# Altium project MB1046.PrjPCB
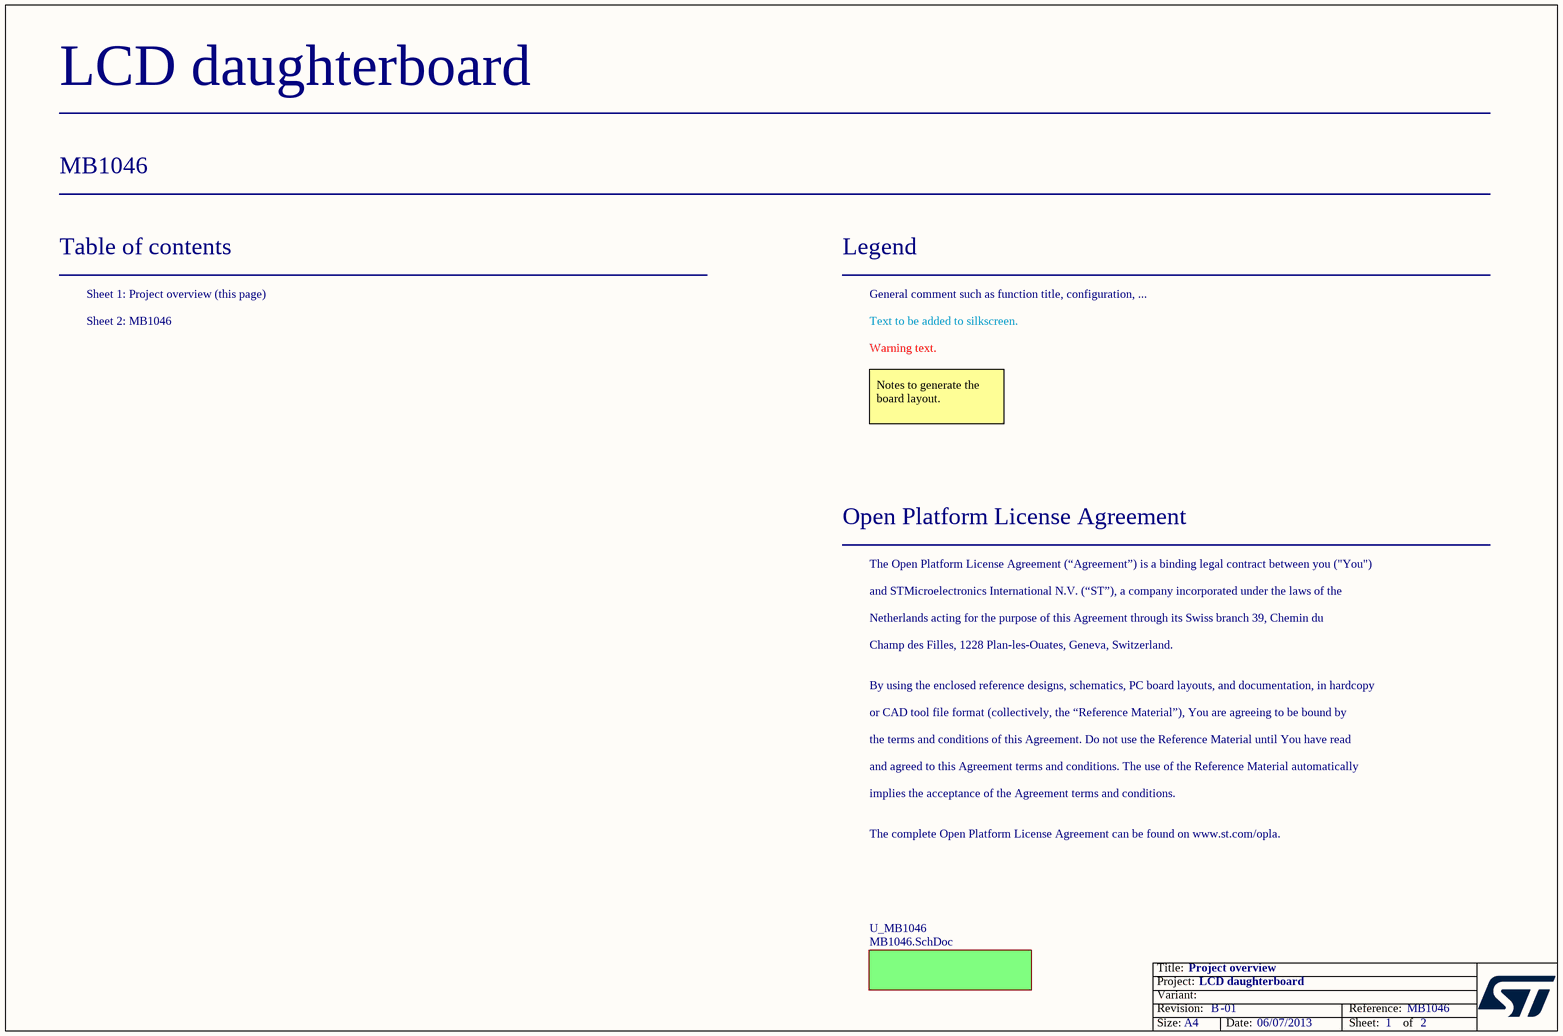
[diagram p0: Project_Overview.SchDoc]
Board_Assembly_Revision: 01; Board_Document_Date: 06/07/2013; Board_Name: LCD daughterboard; Board_PCB_Revision: B; Board_Reference: MB1046
2 sheets, 46 parts. Net scope: global (net labels, ports and power ports of the same name join across sheets).
Sheets:
  Project_Overview.SchDoc
    U_MB1046 = MB1046.SchDoc

## Sheet Project_Overview.SchDoc: Project overview
size A4; Date: Not used; ApprovedBy: Not used; CheckedBy: Not used; Author: Not used; CompanyName: STMicroelectronics; DrawnBy: Not used; Engineer: Not used; Organization: Not used; Address1: Not used; Address2: Not used; Address3: Not used; Address4: Not used; DocumentNumber: 1; Revision: Not used; SheetNumber: 1; SheetTotal: 2

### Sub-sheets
U_MB1046 = MB1046.SchDoc: no entries

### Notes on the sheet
- Table of contents
- Sheet 1: Project overview (this page)
- Legend
- General comment such as function title, configuration, ...
- Sheet 2: MB1046
- Text to be added to silkscreen.
- Warning text.
- Notes to generate the board layout.
- Open Platform License Agreement
- The Open Platform License Agreement (“Agreement”) is a binding legal contract between you ("You")
- and STMicroelectronics International N.V. (“ST”), a company incorporated under the laws of the
- Netherlands acting for the purpose of this Agreement through its Swiss branch 39, Chemin du
- Champ des Filles, 1228 Plan-les-Ouates, Geneva, Switzerland.
- By using the enclosed reference designs, schematics, PC board layouts, and documentation, in hardcopy
- or CAD tool file format (collectively, the “Reference Material”), You are agreeing to be bound by
- the terms and conditions of this Agreement. Do not use the Reference Material until You have read
- and agreed to this Agreement terms and conditions. The use of the Reference Material automatically
- implies the acceptance of the Agreement terms and conditions.
- The complete Open Platform License Agreement can be found on www.st.com/opla.

## Sheet MB1046.SchDoc: 4.3 inch LCD board
size A4; DocumentNumber: 2; Revision: B.1(PCB.SCH); SheetNumber: 2; SheetTotal: 2
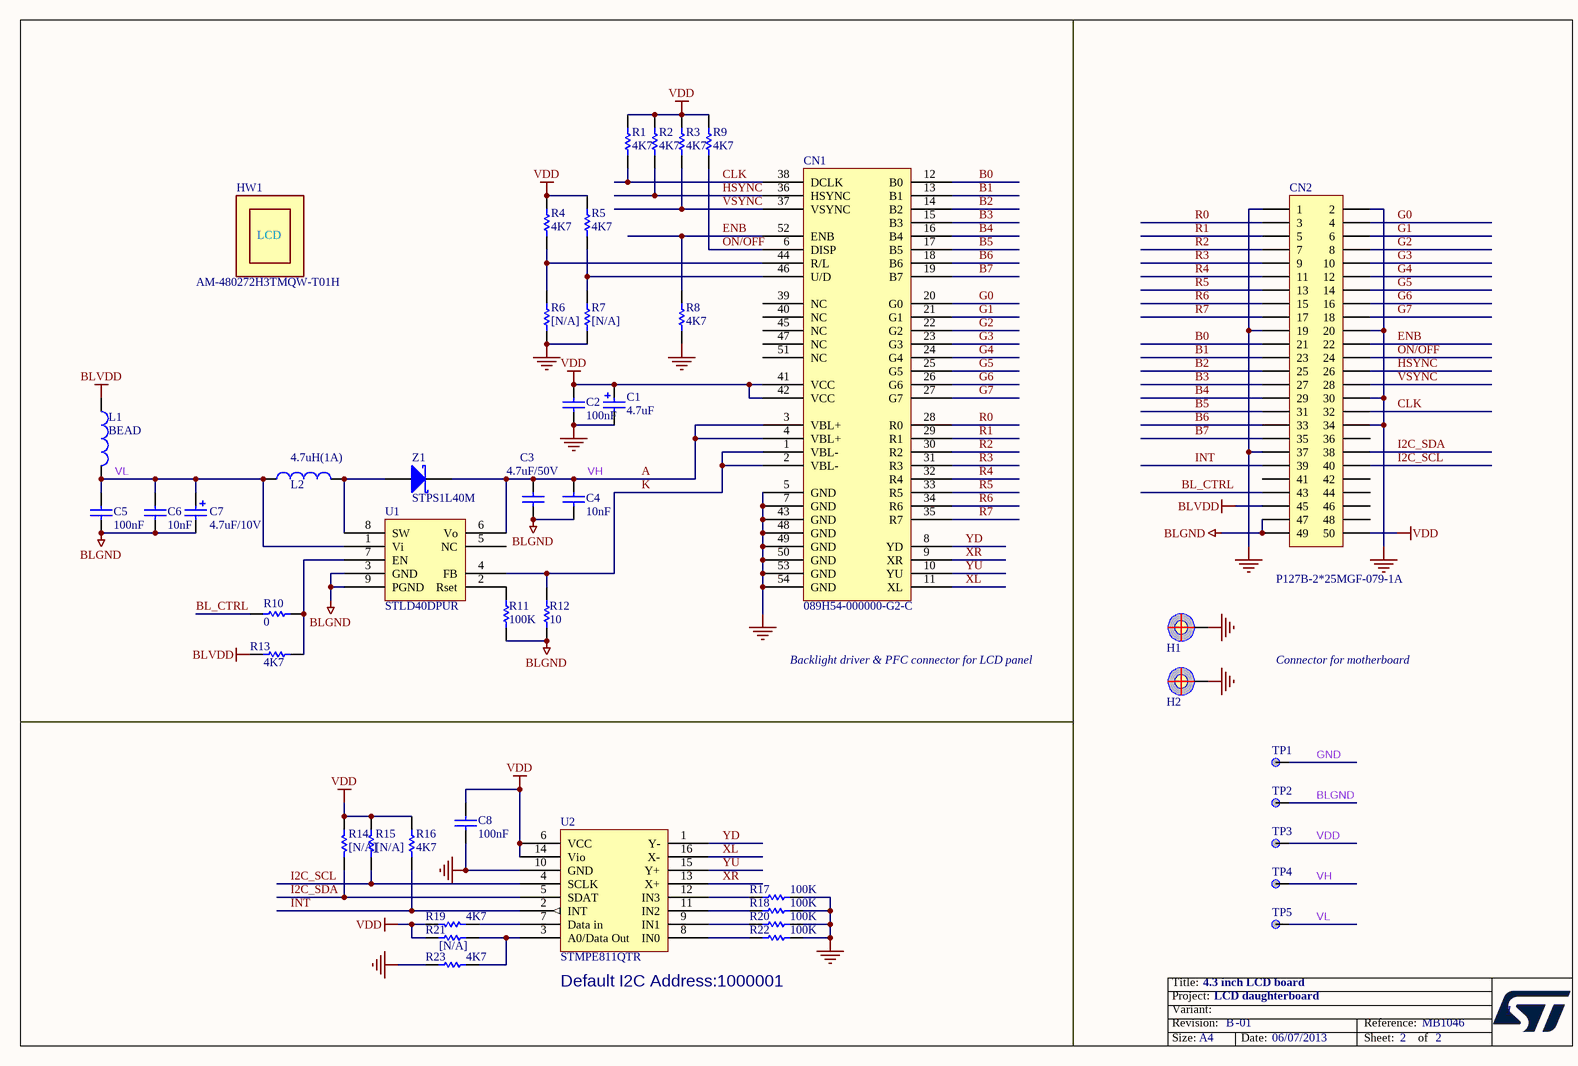
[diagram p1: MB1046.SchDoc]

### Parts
C1  4.7uF  [TAN-A]
C2  100nF  [0603C]
C3  4.7uF/50V  [1206C]
C4  10nF  [0603C]
C5  100nF  [0603C]
C6  10nF  [0603C]
C7  4.7uF/10V  [1206C]
C8  100nF  [0603C]
CN1  089H54-000000-G2-C  [FPC54_0R5_089H54_LY-FPC]
CN2  P127B-2*25MGF-079-1A  [FTSH-125-01-F-DV]
H1  POSITION HOLE  [HOLE_C9D4R5]  (value not drawn)
H2  POSITION HOLE  [HOLE_C9D4R5]  (value not drawn)
HW1  AM-480272H3TMQW-T01H  (mechanical)
L1  BEAD  [0603L]
L2  4.7uH(1A)  [1210L]
R1  4K7  [0603R]
R2  4K7  [0603R]
R3  4K7  [0603R]
R4  4K7  [0603R]
R5  4K7  [0603R]
R6  [N/A]  [0603R]
R7  [N/A]  [0603R]
R8  4K7  [0603R]
R9  4K7  [0603R]
R10  0  [0603R]
R11  100K  [0603R]
R12  10  [0603R]
R13  4K7  [0603R]
R14  [N/A]  [0603R]
R15  [N/A]  [0603R]
R16  4K7  [0603R]
R17  100K  [0603R]
R18  100K  [0603R]
R19  4K7  [0603R]
R20  100K  [0603R]
R21  [N/A]  [0603R]
R22  100K  [0603R]
R23  4K7  [0603R]
TP1  (no value)  [TP]
TP2  (no value)  [TP]
TP3  (no value)  [TP]
TP4  (no value)  [TP]
TP5  (no value)  [TP]
U1  STLD40DPUR  [SON8_0R65_3X3]
U2  STMPE811QTR  [QFN16_0R5_3X3]
Z1  STPS1L40M  [DO-216AA]

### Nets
BLGND: C3.2 C4.1 C5.1 C6.1 C7.2 CN2.47 CN2.49 R11.2 R12.1 TP2.1 U1.3(GND) U1.9(PGND)
BLVDD: CN2.45 L1.1 R13.2
GND: C1.2 C2.1 C8.2 CN1.5(GND) CN1.7(GND) CN1.43(GND) CN1.48(GND) CN1.49(GND) CN1.50(GND) CN1.53(GND) CN1.54(GND) CN2.1 CN2.2 CN2.19 CN2.20 CN2.30 CN2.34 CN2.37 H1.1 H2.1 R6.2 R7.2 R8.2 R17.1 R18.1 R20.1 R22.1 R23.1 TP1.1 U2.10(GND)
VDD: C1.1 C2.2 C8.1 CN1.41(VCC) CN1.42(VCC) CN2.50 R1.1 R2.1 R3.1 R4.1 R5.1 R9.1 R14.2 R15.2 R16.1 R19.2 R21.2 TP3.1 U2.6(VCC) U2.14(Vio)
A: C3.1 C4.2 CN1.3(VBL+) CN1.4(VBL+) TP4.1 U1.6(Vo) Z1.2(K)  [also labelled VH]
B0: CN1.12(B0) CN2.21
B1: CN1.13(B1) CN2.23
B2: CN1.14(B2) CN2.25
B3: CN1.15(B3) CN2.27
B4: CN1.16(B4) CN2.29
B5: CN1.17(B5) CN2.31
B6: CN1.18(B6) CN2.33
B7: CN1.19(B7) CN2.35
BL_CTRL: CN2.43 R10.2
CLK: CN1.38(DCLK) CN2.32 R1.2
ENB: CN1.52(ENB) CN2.22 R8.1
G0: CN1.20(G0) CN2.4
G1: CN1.21(G1) CN2.6
G2: CN1.22(G2) CN2.8
G3: CN1.23(G3) CN2.10
G4: CN1.24(G4) CN2.12
G5: CN1.25(G5) CN2.14
G6: CN1.26(G6) CN2.16
G7: CN1.27(G7) CN2.18
HSYNC: CN1.36(HSYNC) CN2.26 R2.2
I2C_SCL: CN2.40 R15.1 U2.4(SCLK)
I2C_SDA: CN2.38 R14.1 U2.5(SDAT)
INT: CN2.39 R16.2 U2.2(INT)
K: CN1.1(VBL-) CN1.2(VBL-) R12.2 U1.4(FB)
ON/OFF: CN1.6(DISP) CN2.24 R9.2
R0: CN1.28(R0) CN2.3
R1: CN1.29(R1) CN2.5
R2: CN1.30(R2) CN2.7
R3: CN1.31(R3) CN2.9
R4: CN1.32(R4) CN2.11
R5: CN1.33(R5) CN2.13
R6: CN1.34(R6) CN2.15
R7: CN1.35(R7) CN2.17
VL: C5.2 C6.2 C7.1 L1.2 L2.1 TP5.1 U1.1(Vi)
VSYNC: CN1.37(VSYNC) CN2.28 R3.2
XL: CN1.11(XL) U2.16(X-)
XR: CN1.9(XR) U2.13(X+)
YD: CN1.8(YD) U2.1(Y-)
YU: CN1.10(YU) U2.15(Y+)
NetCN1_44: CN1.44(R/L) R4.2 R6.1
NetCN1_46: CN1.46(U/D) R5.2 R7.1
NetL2_2: L2.2 U1.8(SW) Z1.1(A)
NetR10_1: R10.1 R13.1 U1.7(EN)
NetR11_1: R11.1 U1.2(Rset)
NetR17_2: R17.2 U2.12(IN3)
NetR18_2: R18.2 U2.11(IN2)
NetR19_1: R19.1 U2.7(Data_in)
NetR20_2: R20.2 U2.9(IN1)
NetR21_1: R21.1 R23.2 U2.3(A0/Data_Out)
NetR22_2: R22.2 U2.8(IN0)

Not connected (* = marked no-connect by the designer): CN1 39(NC) 40(NC) 45(NC) 47(NC) 51(NC); CN2 36 41 42 44 46 48; U1 5(NC)

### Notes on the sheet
- Backlight driver & PFC connector for LCD panel
- Connector for motherboard
- Default I2C Address:1000001
- 1

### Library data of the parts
C1 C7 = Cap Pol1: Polarized Capacitor (Radial); Value: 100pF
C2-C6 C8 = CAP: Capacitor; Value: 100pF
CN2 = Header 25X2: Header, 26-Pin, Dual row
HW1 = LCD_MODULE
L1 L2 = Inductor: Value: 100uH
R1-R16 R19 R21 R23 = Res1: Resistor; Value: 1K
R17 R18 R20 R22 = res1: Resistor
TP1-TP5 = TP
U1 = STLD40DPMR
U2 = STMPE811
Z1 = D Schottky: Schottky Diode; Code - JEDEC: DO-214-AA

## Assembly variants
Default: not fitted R6 R7 R14 R15 R21 TP1 TP2 TP3 TP4 TP5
